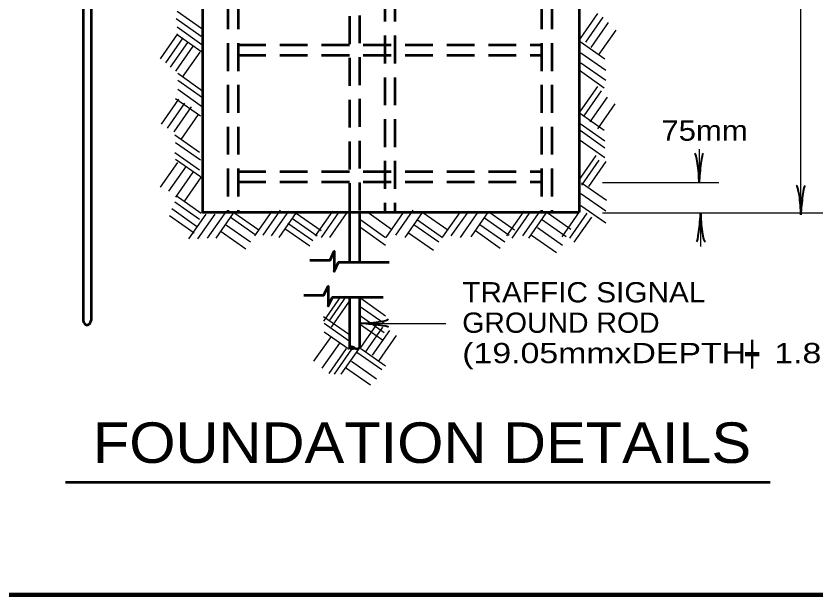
# Model space of a CAD drawing. Extents: x -711 to 145, y 25 to 569.
# Drawn here: x -347.5 to -252.6, y 36.6 to 105.2 of the extents above; entities that cross this region are included whole.
import ezdxf

# ---------------------------------------------------------------- set-up
doc = ezdxf.new("R2010")
doc.units = 0
doc.header["$LTSCALE"] = 1.1
doc.linetypes.add('MEDIUM_DASHED', pattern=[4.5, 3, -1.5])
doc.layers.add('1', color=7, linetype='Continuous', lineweight=53)

msp = doc.modelspace()

# ---------------------------------------------------------------- linework, layer by layer
at = {"layer": '1', "linetype": 'MEDIUM_DASHED'}
for p, q in [((-307.925, 169.498), (-307.925, 81.935)), ((-306.725, 169.588), (-306.725, 81.935)), ((-322.325, 166.298), (-322.325, 81.935)), ((-321.125, 166.298), (-321.125, 81.935)), ((-285.125, 166.298), (-285.125, 81.935)), ((-283.925, 166.298), (-283.925, 81.935)), ((-303.725, 147.399), (-303.725, 81.935)), ((-302.525, 147.399), (-302.525, 81.935)), ((-321.125, 101.735), (-285.125, 101.735)), ((-321.125, 100.535), (-285.125, 100.535)), ((-321.125, 86.735), (-285.125, 86.735)), ((-321.125, 85.535), (-285.125, 85.535))]:
    msp.add_line(p, q, dxfattribs=at)
at = {"layer": '1', "lineweight": 25}
for p, q in [((-254.382, 81.637), (-254.382, 169.492)), ((-328.364, 105.76), (-325.415, 103.696)), ((-280.528, 102.521), (-278.463, 105.47)), ((-328.454, 104.86), (-325.505, 102.795)), ((-279.897, 102.071), (-277.833, 105.02)), ((-279.267, 101.44), (-277.202, 104.389)), ((-328.364, 103.87), (-325.415, 101.805)), ((-278.367, 100.54), (-276.302, 103.489)), ((-330.311, 100.09), (-328.247, 103.039)), ((-329.681, 99.64), (-327.616, 102.589)), ((-328.364, 102.97), (-325.415, 100.905)), ((-329.141, 99.1), (-327.076, 102.049)), ((-328.511, 98.65), (-326.446, 101.598)), ((-280.561, 102.159), (-277.612, 100.095)), ((-327.701, 97.929), (-325.636, 100.878)), ((-280.471, 100.809), (-277.522, 98.744)), ((-280.471, 99.639), (-277.522, 97.574)), ((-280.651, 98.738), (-277.702, 96.674)), ((-328.274, 98.378), (-325.325, 96.314)), ((-328.274, 97.568), (-325.325, 95.503)), ((-280.528, 93.878), (-278.463, 96.827)), ((-328.274, 96.488), (-325.325, 94.423)), ((-280.077, 93.338), (-278.013, 96.287)), ((-330.221, 92.348), (-328.156, 95.297)), ((-328.544, 95.407), (-325.595, 93.343)), ((-279.357, 92.618), (-277.293, 95.567)), ((-329.501, 91.898), (-327.436, 94.847)), ((-328.691, 91.448), (-326.626, 94.397)), ((-278.457, 91.808), (-276.392, 94.757)), ((-327.881, 90.547), (-325.816, 93.496)), ((-280.651, 93.697), (-277.702, 91.632)), ((-280.561, 92.437), (-277.612, 90.372)), ((-328.634, 91.086), (-325.685, 89.022)), ((-280.561, 91.626), (-277.612, 89.562)), ((-328.544, 90.186), (-325.595, 88.121)), ((-280.561, 90.456), (-277.612, 88.391)), ((-266.445, 89.379), (-266.445, 85.444)), ((-328.634, 89.016), (-325.685, 86.951)), ((-280.708, 85.686), (-278.643, 88.635)), ((-330.311, 84.876), (-328.247, 87.825)), ((-329.321, 84.426), (-327.256, 87.374)), ((-328.544, 88.206), (-325.595, 86.141)), ((-280.348, 85.146), (-278.283, 88.095)), ((-279.537, 84.966), (-277.473, 87.915)), ((-328.511, 83.705), (-326.446, 86.654)), ((-327.521, 83.165), (-325.456, 86.114)), ((-280.381, 85.415), (-277.432, 83.35)), ((-277.909, 85.444), (-264.109, 85.444)), ((-328.454, 83.884), (-325.505, 81.819)), ((-280.471, 84.154), (-277.522, 82.09)), ((-328.634, 83.164), (-325.685, 81.099)), ((-280.471, 82.714), (-277.522, 80.649)), ((-328.994, 82.354), (-326.045, 80.289)), ((-326.981, 78.754), (-324.916, 81.703)), ((-325.9, 78.754), (-323.835, 81.703)), ((-324.73, 78.844), (-322.665, 81.793)), ((-323.74, 78.844), (-321.675, 81.793)), ((-321.612, 81.904), (-318.663, 79.839)), ((-319.148, 79.114), (-317.083, 82.063)), ((-318.158, 79.204), (-316.093, 82.153)), ((-317.168, 79.114), (-315.103, 82.063)), ((-316.267, 78.934), (-314.203, 81.883)), ((-314.23, 81.814), (-311.281, 79.749)), ((-311.946, 79.114), (-309.882, 82.063)), ((-311.226, 78.934), (-309.161, 81.883)), ((-310.236, 78.934), (-308.171, 81.883)), ((-305.858, 81.994), (-302.909, 79.929)), ((-303.574, 78.934), (-301.509, 81.883)), ((-302.404, 79.204), (-300.339, 82.153)), ((-301.323, 78.934), (-299.259, 81.883)), ((-299.196, 81.904), (-296.247, 79.839)), ((-296.822, 79.024), (-294.757, 81.973)), ((-295.832, 79.114), (-293.767, 82.063)), ((-294.752, 78.934), (-292.687, 81.883)), ((-293.491, 79.024), (-291.426, 81.973)), ((-291.274, 81.904), (-288.325, 79.839)), ((-289.26, 79.114), (-287.195, 82.063)), ((-288.63, 78.844), (-286.565, 81.793)), ((-287.369, 79.114), (-285.305, 82.063)), ((-286.649, 78.844), (-284.584, 81.793)), ((-284.612, 81.994), (-281.663, 79.929)), ((-282.688, 79.024), (-280.623, 81.973)), ((-281.788, 78.844), (-279.723, 81.793)), ((-277.909, 81.866), (-251.509, 81.866)), ((-266.265, 81.866), (-266.265, 77.857)), ((-329.264, 81.544), (-326.315, 79.479)), ((-322.062, 81.364), (-319.113, 79.299)), ((-315.22, 80.643), (-312.271, 78.579)), ((-314.68, 81.184), (-311.731, 79.119)), ((-306.578, 81.003), (-303.629, 78.939)), ((-299.826, 81.003), (-296.877, 78.939)), ((-291.904, 81.273), (-288.955, 79.209)), ((-285.152, 81.094), (-282.203, 79.029)), ((-281.248, 78.394), (-279.183, 81.343)), ((-322.602, 80.463), (-319.653, 78.398)), ((-315.58, 80.013), (-312.631, 77.948)), ((-306.578, 80.103), (-303.629, 78.038)), ((-300.276, 80.463), (-297.327, 78.398)), ((-292.984, 79.743), (-290.035, 77.678)), ((-292.444, 80.463), (-289.495, 78.398)), ((-285.602, 80.103), (-282.653, 78.038)), ((-323.142, 79.653), (-320.193, 77.588)), ((-300.906, 79.473), (-297.957, 77.408)), ((-286.322, 79.203), (-283.373, 77.138)), ((-310.956, 69.031), (-308.891, 71.98)), ((-310.326, 69.031), (-308.261, 71.98)), ((-310.056, 68.311), (-307.991, 71.26)), ((-306.578, 71.731), (-303.629, 69.666)), ((-306.758, 70.831), (-303.809, 68.766)), ((-310.989, 69.57), (-308.04, 67.505)), ((-306.758, 69.75), (-303.809, 67.686)), ((-310.899, 68.76), (-307.95, 66.695)), ((-306.732, 68.757), (-296.469, 68.757)), ((-306.724, 68.7), (-303.989, 66.785)), ((-306.635, 65.791), (-304.57, 68.74)), ((-310.899, 67.77), (-307.95, 65.705)), ((-306.005, 65.34), (-303.94, 68.289)), ((-305.194, 64.98), (-303.13, 67.929)), ((-312.126, 64.26), (-310.062, 67.209)), ((-304.384, 64.35), (-302.319, 67.299)), ((-311.136, 63.45), (-309.071, 66.399)), ((-310.326, 62.82), (-308.261, 65.769)), ((-309.696, 62.73), (-307.631, 65.679)), ((-308.886, 62.73), (-306.821, 65.679)), ((-306.578, 65.789), (-303.629, 63.725)), ((-307.028, 65.339), (-304.079, 63.274)), ((-307.658, 64.259), (-304.709, 62.194)), ((-308.378, 63.539), (-305.429, 61.474))]:
    msp.add_line(p, q, dxfattribs=at)
at = {"layer": '1'}
for p, q in [((-280.687, 166.888), (-280.687, 81.935)), ((-339.509, 138.321), (-339.509, 69.075)), ((-338.548, 138.321), (-338.548, 69.075)), ((-307.924, 81.954), (-307.924, 75.954)), ((-306.726, 81.965), (-306.726, 75.965)), ((-307.924, 71.873), (-307.924, 65.873)), ((-306.724, 71.873), (-306.724, 65.873)), ((-339.029, 68.563), (-339.029, 68.456)), ((-307.316, 65.831), (-307.354, 65.866)), ((-341.577, 49.924), (-258.014, 49.924))]:
    msp.add_line(p, q, dxfattribs=at)
at = {"layer": '1', "lineweight": 158}
msp.add_line((138.105, 36.575), (-653.495, 36.575), dxfattribs=at)
at = {"layer": '1'}
for points in [[(-325.325, 165.892), (-325.325, 81.935), (-280.687, 81.935)], [(-312.616, 76.231), (-310.216, 76.231), (-309.709, 77.318), (-309.709, 74.918), (-309.201, 76.006), (-303.201, 76.006)], [(-313.336, 72.09), (-310.936, 72.09), (-310.429, 73.178), (-310.429, 70.778), (-309.921, 71.865), (-303.921, 71.865)]]:
    msp.add_lwpolyline(points, dxfattribs=at)
for centre, start, end in [((-338.855, 69.204), 191.11811, 254.886), ((-339.202, 69.204), 285.114, 348.88189)]:
    msp.add_arc(centre, 0.666, start, end, dxfattribs=at)
at = {"layer": '1', "lineweight": 40}
for centre, major_axis, ratio, start_param, end_param in [((-266.777, 86.753), (0.187, -2.143), 0.122415, 0.896353, 3.141593), ((-266.191, 86.788), (0.211, 2.108), 0.07063, 6.282307, 8.559703), ((-254.714, 82.946), (0.187, -2.143), 0.122415, 0.896353, 3.141593), ((-254.128, 82.981), (0.211, 2.108), 0.07063, 6.282307, 8.559703), ((-266.519, 80.521), (-0.211, -2.108), 0.07063, 6.282307, 8.559703), ((-265.934, 80.556), (-0.187, 2.143), 0.122415, 0.896353, 3.141593), ((-305.422, 69.089), (-2.143, -0.187), 0.122415, 0.896353, 3.141593), ((-305.387, 68.503), (2.108, -0.211), 0.07063, 6.282307, 8.559703)]:
    msp.add_ellipse(centre, major_axis=major_axis, ratio=ratio, start_param=start_param, end_param=end_param, dxfattribs=at)
at = {"layer": '1'}
for centre, major_axis, ratio, start_param, end_param in [((-307.61, 66.209), (-0.313, -0.329), 0.942572, 0, 1.410778), ((-307.604, 65.549), (-0.313, 0.329), 0.870662, 4.860384, 6.283185), ((-307.033, 66.209), (0.343, 0.326), 0.960356, 3.318039, 4.712389)]:
    msp.add_ellipse(centre, major_axis=major_axis, ratio=ratio, start_param=start_param, end_param=end_param, dxfattribs=at)

# ---------------------------------------------------------------- texts
for s, height, width, p in [('75mm', 2.4, 1.15, (-270.927, 90.395)), ('TRAFFIC SIGNAL', 2.4, 1.1, (-294.535, 71.238)), ('GROUND ROD', 2.4, 1.05, (-294.535, 67.638)), ('(19.05mmxDEPTH   1.8m)', 2.4, 1.25, (-294.535, 64.038)), ('+', 4.8, 0.55, (-261.188, 62.785)), ('FOUNDATION DETAILS', 4.8, 1.1, (-338.341, 52.221))]:
    msp.add_text(s, height=height, dxfattribs=dict(at, width=width)).set_placement(p)

doc.saveas('drawing.dxf')
